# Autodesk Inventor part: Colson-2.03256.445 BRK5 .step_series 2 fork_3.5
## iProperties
Created: 2010-10
Part Number: Colson-2.03256.445 BRK5 .step_series 2 fork_3.5
Document SubType Name: Modeling
Designer: Administrator
Density: 7.85 g/cm^3
Material: Steel
Mass: 181.925 g
Surface Area: 201.14 cm^2
Volume: 23.1752 cm^3
Author: Administrator
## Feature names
1. Base1
